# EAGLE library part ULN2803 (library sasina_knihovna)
Tranzistorove pole.
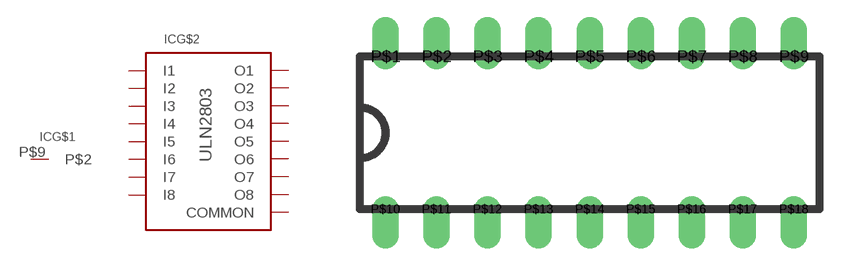
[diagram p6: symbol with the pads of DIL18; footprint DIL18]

Designator prefix IC; gates G$1=NAPAJENI_GND G$2=ULN2803

## ULN2803  [DIL18]
P$1  G$2:I1  in
P$2  G$2:I2  in
P$3  G$2:I3  in
P$4  G$2:I4  in
P$5  G$2:I5  in
P$6  G$2:I6  in
P$7  G$2:I7  in
P$8  G$2:I8  in
P$9  G$1:P$2  pwr
P$10  G$2:COMMON  pas
P$11  G$2:O8  oc
P$12  G$2:O7  oc
P$13  G$2:O6  oc
P$14  G$2:O5  oc
P$15  G$2:O4  oc
P$16  G$2:O3  oc
P$17  G$2:O2  oc
P$18  G$2:O1  oc

## Footprint DIL18 (pad centres in mm)
drill 0.8 offset: P$1 -10.16,3.81; P$2 -7.62,3.81; P$3 -5.08,3.81; P$4 -2.54,3.81; P$5 0,3.81; P$6 2.54,3.81; P$7 5.08,3.81; P$8 7.62,3.81; P$9 10.16,3.81; P$10 -10.16,-3.81; P$11 -7.62,-3.81; P$12 -5.08,-3.81; P$13 -2.54,-3.81; P$14 0,-3.81; P$15 2.54,-3.81; P$16 5.08,-3.81; P$17 7.62,-3.81; P$18 10.16,-3.81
